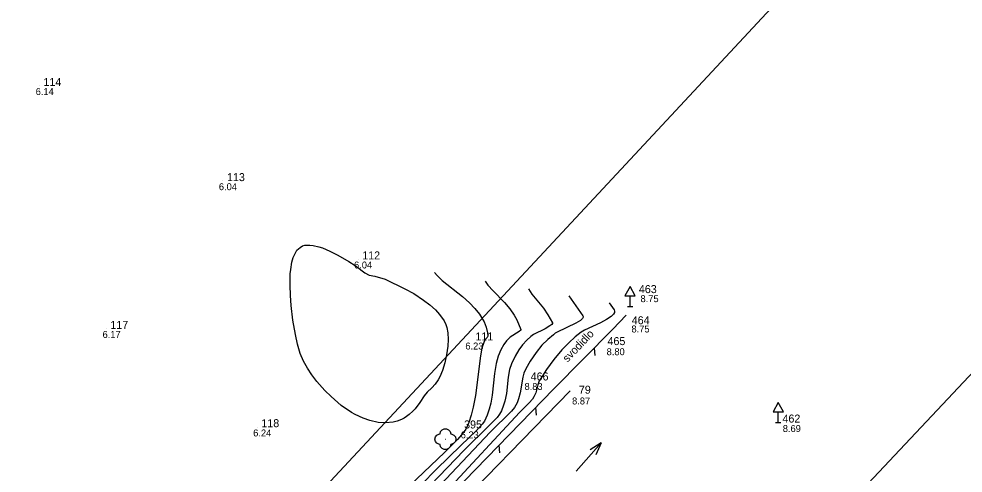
# Model space of a CAD drawing. Extents: x -792549 to -792339, y -1111914 to -1111617.
# Drawn here: x -792457.02 to -792412.17, y -1111679.36 to -1111657.78 of the extents above; entities that cross this region are included whole.
import ezdxf

# ---------------------------------------------------------------- set-up
doc = ezdxf.new("R2010")
doc.units = 0
for name, color, linetype in [('Vrstva 1', 7, 'Continuous'), ('Vrstva 32', 7, 'Continuous'), ('Vrstva 33', 7, 'Continuous'), ('Vrstva 41', 7, 'Continuous'), ('Vrstva 44', 7, 'Continuous'), ('Vrstva 45', 7, 'Continuous'), ('Vrstva 46', 7, 'Continuous'), ('Vrstva 48', 7, 'Continuous'), ('Vrstva 49', 7, 'Continuous'), ('Vrstva 50', 7, 'Continuous'), ('Vrstva 52', 7, 'Continuous')]:
    doc.layers.add(name, color=color, linetype=linetype)

# ---------------------------------------------------------------- blocks, each defined once
blk = doc.blocks.new('5$2930')
at = {"layer": 'Vrstva 1'}
blk.add_line((0, 0), (10, 10), dxfattribs=at)
blk = doc.blocks.new('SC6231')
at = {"layer": 'Vrstva 1'}
blk.add_line((0, 0), (0, 0), dxfattribs=at)
blk = doc.blocks.new('3$1301')
at = {"layer": 'Vrstva 1'}
for points in [[(20, 0), (19, -4.3), (16.2, -7.8), (12.2, -9.7), (10, -10), (9, -14.3), (6.2, -17.8), (2.2, -19.7), (-2.3, -19.7), (-6.3, -17.8), (-9.1, -14.3), (-10.1, -10), (-12.3, -9.7), (-16.3, -7.8), (-19.1, -4.3), (-20.1, 0), (-19.1, 4.3), (-16.3, 7.8), (-12.3, 9.7), (-10.1, 10), (-9.1, 14.3), (-6.3, 17.8), (-2.3, 19.7), (2.2, 19.7), (6.2, 17.8), (9, 14.3), (10, 10), (12.2, 9.7), (16.2, 7.8), (19, 4.3), (20, 0)], [(-0.5, 0), (0, 0), (0.5, 0)]]:
    blk.add_lwpolyline(points, dxfattribs=at)
blk = doc.blocks.new('5$2700')
at = {"layer": 'Vrstva 1'}
blk.add_line((-5, 0), (5, 0), dxfattribs=at)
blk.add_lwpolyline([(0, 0), (0, 20), (10, 20), (0, 37.5), (-10, 20), (0, 20)], dxfattribs=at)

msp = doc.modelspace()

# ---------------------------------------------------------------- linework, layer by layer
at = {"layer": 'Vrstva 32'}
for points in [[(-792441.05, -1111669.503), (-792440.585, -1111669.848), (-792440.381, -1111669.953), (-792440.109, -1111670.007), (-792439.628, -1111670.141), (-792438.679, -1111670.603), (-792438.267, -1111670.83), (-792437.801, -1111671.139), (-792437.496, -1111671.372), (-792437.233, -1111671.6), (-792437.044, -1111671.82), (-792436.826, -1111672.126), (-792436.741, -1111672.297), (-792436.695, -1111672.441), (-792436.649, -1111672.697), (-792436.628, -1111673.017), (-792436.647, -1111673.323), (-792436.706, -1111673.744), (-792436.792, -1111674.128), (-792436.901, -1111674.481), (-792437.03, -1111674.788), (-792437.11, -1111674.932), (-792437.253, -1111675.134), (-792437.411, -1111675.317), (-792437.624, -1111675.514), (-792437.765, -1111675.692), (-792437.967, -1111676.005), (-792438.192, -1111676.304), (-792438.307, -1111676.425), (-792438.474, -1111676.58), (-792438.6, -1111676.678), (-792438.714, -1111676.748), (-792438.853, -1111676.818), (-792439.056, -1111676.893), (-792439.239, -1111676.946), (-792439.599, -1111676.975), (-792439.954, -1111676.95), (-792440.349, -1111676.866), (-792440.673, -1111676.75), (-792441.048, -1111676.571), (-792441.217, -1111676.48), (-792441.71, -1111676.142), (-792442.192, -1111675.726), (-792442.485, -1111675.433), (-792442.86, -1111675.007), (-792443.101, -1111674.698), (-792443.314, -1111674.379), (-792443.498, -1111674.05), (-792443.655, -1111673.68), (-792443.786, -1111673.234), (-792443.885, -1111672.784), (-792443.999, -1111672.097), (-792444.08, -1111671.396), (-792444.115, -1111670.92), (-792444.133, -1111670.433), (-792444.125, -1111669.891), (-792444.105, -1111669.687), (-792444.047, -1111669.34), (-792443.996, -1111669.119), (-792443.82, -1111668.776), (-792443.659, -1111668.646), (-792443.55, -1111668.572), (-792443.437, -1111668.539), (-792443.323, -1111668.529), (-792443.205, -1111668.53), (-792443.041, -1111668.546), (-792442.77, -1111668.607), (-792442.591, -1111668.666), (-792442.256, -1111668.81), (-792441.863, -1111669.01), (-792441.349, -1111669.307), (-792441.05, -1111669.503)], [(-792434.869, -1111670.247), (-792434.743, -1111670.426), (-792434.486, -1111670.71), (-792433.952, -1111671.261), (-792433.695, -1111671.564), (-792433.491, -1111671.855), (-792433.362, -1111672.087), (-792433.173, -1111672.532), (-792433.183, -1111672.572), (-792433.257, -1111672.637), (-792433.687, -1111672.898), (-792433.859, -1111673.078), (-792433.992, -1111673.256), (-792434.13, -1111673.5), (-792434.261, -1111673.805), (-792434.356, -1111674.162), (-792434.423, -1111674.629), (-792434.538, -1111675.66), (-792434.604, -1111676.038), (-792434.677, -1111676.319), (-792434.78, -1111676.608), (-792434.911, -1111676.889), (-792435.013, -1111677.032), (-792435.286, -1111677.336), (-792436.025, -1111678.057), (-792437.19, -1111679.178), (-792439.327, -1111681.365)], [(-792430.895, -1111670.936), (-792430.23, -1111671.89), (-792430.213, -1111671.923), (-792430.211, -1111671.961), (-792430.245, -1111672.024), (-792430.351, -1111672.117), (-792430.558, -1111672.244), (-792431.456, -1111672.669), (-792431.545, -1111672.721), (-792431.633, -1111672.785), (-792431.899, -1111673.007), (-792432.176, -1111673.289), (-792432.456, -1111673.637), (-792432.73, -1111674.048), (-792432.938, -1111674.411), (-792433.031, -1111674.619), (-792433.086, -1111674.803), (-792433.21, -1111675.554), (-792433.283, -1111675.834), (-792433.354, -1111676.021), (-792433.474, -1111676.245), (-792433.615, -1111676.416), (-792434.629, -1111677.413), (-792438.311, -1111681.312)]]:
    msp.add_lwpolyline(points, dxfattribs=at)
at = {"layer": 'Vrstva 33'}
for points in [[(-792437.277, -1111669.83), (-792437.157, -1111669.98), (-792436.911, -1111670.206), (-792435.952, -1111670.974), (-792435.609, -1111671.279), (-792435.355, -1111671.542), (-792435.145, -1111671.806), (-792434.992, -1111672.046), (-792434.926, -1111672.176), (-792434.831, -1111672.422), (-792434.763, -1111672.701), (-792434.739, -1111672.857), (-792434.783, -1111672.923), (-792434.83, -1111672.969), (-792434.869, -1111673.022), (-792434.94, -1111673.158), (-792435.026, -1111673.418), (-792435.094, -1111673.794), (-792435.335, -1111675.668), (-792435.437, -1111676.235), (-792435.531, -1111676.613), (-792435.647, -1111676.961), (-792435.794, -1111677.275), (-792435.911, -1111677.454), (-792436.182, -1111677.763), (-792436.795, -1111678.38), (-792439.787, -1111681.215)], [(-792432.818, -1111670.603), (-792432.648, -1111670.853), (-792432.106, -1111671.533), (-792431.899, -1111671.84), (-792431.68, -1111672.227), (-792431.679, -1111672.254), (-792431.707, -1111672.297), (-792431.794, -1111672.367), (-792432.028, -1111672.501), (-792432.574, -1111672.773), (-792432.707, -1111672.872), (-792432.893, -1111673.041), (-792433.098, -1111673.27), (-792433.269, -1111673.505), (-792433.446, -1111673.8), (-792433.625, -1111674.17), (-792433.709, -1111674.435), (-792433.773, -1111674.808), (-792433.864, -1111675.582), (-792433.935, -1111675.938), (-792433.993, -1111676.134), (-792434.103, -1111676.399), (-792434.187, -1111676.564), (-792434.306, -1111676.721), (-792434.611, -1111677.042), (-792435.892, -1111678.282), (-792439.02, -1111681.554)], [(-792428.979, -1111671.269), (-792428.738, -1111671.609), (-792428.721, -1111671.664), (-792428.733, -1111671.724), (-792428.782, -1111671.809), (-792428.893, -1111671.922), (-792429.105, -1111672.07), (-792429.398, -1111672.227), (-792430.156, -1111672.571), (-792430.319, -1111672.673), (-792430.601, -1111672.892), (-792430.905, -1111673.171), (-792431.223, -1111673.51), (-792431.605, -1111673.972), (-792431.955, -1111674.441), (-792432.265, -1111674.919), (-792432.3, -1111674.984), (-792432.367, -1111675.171), (-792432.472, -1111675.549), (-792432.56, -1111675.744), (-792432.621, -1111675.845), (-792432.789, -1111676.03), (-792433.235, -1111676.479), (-792436.677, -1111680.19)]]:
    msp.add_lwpolyline(points, dxfattribs=at)
at = {"layer": 'Vrstva 41'}
msp.add_line((-792456.34, -1111722.07), (-792402.71, -1111664.98), dxfattribs=at)
msp.add_lwpolyline([(-792396.21, -1111631.51), (-792404.9, -1111639.66), (-792454.29, -1111692.72), (-792461.78, -1111700.29), (-792461.99, -1111689.5), (-792462.65, -1111684.23), (-792458.31, -1111684.1), (-792457.6, -1111689.12), (-792454.29, -1111692.72)], dxfattribs=at)
at = {"layer": 'Vrstva 45'}
for p, q in [((-792430.55, -1111679.27), (-792429.355, -1111677.927)), ((-792429.355, -1111677.927), (-792429.884, -1111678.248)), ((-792429.355, -1111677.927), (-792429.612, -1111678.49))]:
    msp.add_line(p, q, dxfattribs=at)
at = {"layer": 'Vrstva 46'}
msp.add_lwpolyline([(-792428.18, -1111671.86), (-792428.81, -1111672.53), (-792431.61, -1111675.35), (-792442.22, -1111686.28), (-792447.55, -1111691.75), (-792451.19, -1111695.56), (-792454.13, -1111698.57)], dxfattribs=at)
at = {"layer": 'Vrstva 52'}
msp.add_lwpolyline([(-792430.84, -1111675.46), (-792443.34, -1111688.31), (-792451.9, -1111696.88), (-792457.5, -1111701.82)], dxfattribs=at)

# ---------------------------------------------------------------- block references
at = {"layer": 'Vrstva 44', "xscale": 0.025, "yscale": 0.025000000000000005}
msp.add_blockref('3$1301', (-792436.76, -1111677.75), dxfattribs=at)
at = {"layer": 'Vrstva 46', "xscale": 0.025, "yscale": 0.025000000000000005}
for p in [(-792427.99, -1111671.44), (-792420.95, -1111676.95)]:
    msp.add_blockref('5$2700', p, dxfattribs=at)
at = {"layer": 'Vrstva 46'}
for p, xscale, yscale, rotation in [((-792429.69, -1111673.42), 0.025, 0.024999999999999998, -130.865546), ((-792432.48, -1111676.25), 0.025000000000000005, 0.025, -130.20702100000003), ((-792434.22, -1111678.04), 0.025000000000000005, 0.025, -130.20702100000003)]:
    msp.add_blockref('5$2930', p, dxfattribs=dict(at, xscale=xscale, yscale=yscale, rotation=rotation))
at = {"layer": 'Vrstva 48', "xscale": 0.1, "yscale": 0.10000000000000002}
for p in [(-792456.03, -1111660.96), (-792447.33, -1111665.48), (-792440.91, -1111669.2), (-792427.99, -1111671.44), (-792428.18, -1111671.86), (-792452.87, -1111672.5), (-792428.81, -1111672.53), (-792435.64, -1111673.05), (-792431.61, -1111675.35), (-792430.84, -1111675.46), (-792420.95, -1111676.95), (-792445.7, -1111677.18), (-792436.76, -1111677.75)]:
    msp.add_blockref('SC6231', p, dxfattribs=at)

# ---------------------------------------------------------------- texts
at = {"layer": 'Vrstva 45'}
msp.add_text('svodidlo', height=0.38, rotation=46.238, dxfattribs=at).set_placement((-792430.963, -1111674.119))
at = {"layer": 'Vrstva 49'}
for s, p in [('114', (-792455.85, -1111660.97)), ('113', (-792447.131, -1111665.49)), ('112', (-792440.711, -1111669.21)), ('463', (-792427.571, -1111670.81)), ('464', (-792427.91, -1111672.29)), ('117', (-792452.671, -1111672.51)), ('111', (-792435.333, -1111673.06)), ('465', (-792429.061, -1111673.28)), ('466', (-792432.711, -1111674.96)), ('79', (-792430.421, -1111675.59)), ('118', (-792445.501, -1111677.18)), ('395', (-792435.871, -1111677.24)), ('462', (-792420.751, -1111676.96))]:
    msp.add_text(s, height=0.38, dxfattribs=at).set_placement(p)
at = {"layer": 'Vrstva 50'}
for s, p in [('6.14', (-792456.219, -1111661.4)), ('6.04', (-792447.519, -1111665.92)), ('6.04', (-792441.099, -1111669.64)), ('8.75', (-792427.493, -1111671.24)), ('8.75', (-792427.923, -1111672.68)), ('6.17', (-792453.043, -1111672.94)), ('6.23', (-792435.813, -1111673.49)), ('8.80', (-792429.103, -1111673.76)), ('8.83', (-792433.003, -1111675.41)), ('8.87', (-792430.743, -1111676.1)), ('6.24', (-792445.889, -1111677.62)), ('6.23', (-792436.033, -1111677.71)), ('8.69', (-792420.737, -1111677.41))]:
    msp.add_text(s, height=0.33, dxfattribs=at).set_placement(p)

doc.saveas('drawing.dxf')
